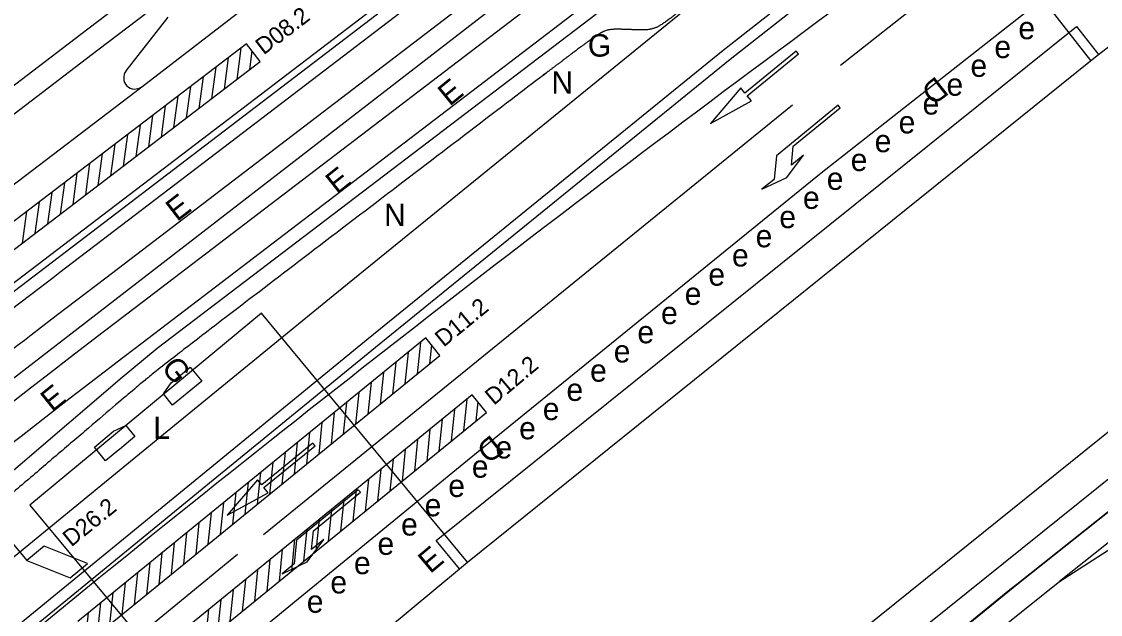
# Model space of a CAD drawing. Extents: x 81617 to 82144, y 454649 to 455150.
# Drawn here: x 81877.73 to 81925.8, y 454919.09 to 454945.52 of the extents above; entities that cross this region are included whole.
import ezdxf

# ---------------------------------------------------------------- set-up
doc = ezdxf.new("R2010")
doc.units = 0
for name, color, linetype in [('B-WE-OG-TOPOGRAFIE-G', 7, 'Continuous'), ('B-WE-VW-MARKERING-G', 7, 'Continuous'), ('N-OI-KL-VRI_KABEL_DETECTIE-G', 7, 'Continuous'), ('N-OI-KL-VRI_KABELGEUL-G', 7, 'Continuous'), ('N-OI-KL-VRI_LUS_DETECTIE-G', 7, 'Continuous'), ('N-OI-KL-VRI_LUS_DETECTIE-T18', 7, 'Continuous')]:
    doc.layers.add(name, color=color, linetype=linetype)

msp = doc.modelspace()

# ---------------------------------------------------------------- linework, layer by layer
at = {"layer": 'B-WE-OG-TOPOGRAFIE-G'}
for p, q in [((81900.482, 454960.292), (81880.371, 454944.941)), ((81923.402, 454955.563), (81908.992, 454944.223)), ((81923.712, 454955.17), (81909.304, 454943.832)), ((81925.37, 454943.778), (81916.494, 454955.166)), ((81925.72, 454944.049), (81935.606, 454951.727)), ((81927.735, 454950.065), (81913.364, 454938.756)), ((81881.134, 454944.252), (81888.032, 454949.528)), ((81883.083, 454942.614), (81889.238, 454947.349)), ((81907.441, 454946.156), (81891.612, 454933.292)), ((81882.384, 454943.318), (81884.261, 454945.72)), ((81880.371, 454944.941), (81861.954, 454930.868)), ((81908.992, 454944.223), (81893.179, 454931.372)), ((81909.304, 454943.832), (81893.495, 454930.984)), ((81864.605, 454928.508), (81883.083, 454942.614)), ((81913.364, 454938.756), (81897.603, 454925.947)), ((81891.612, 454933.292), (81884.055, 454927.107)), ((81888.418, 454932.525), (81878.092, 454923.965)), ((81897.597, 454921.411), (81888.418, 454932.525)), ((81893.179, 454931.372), (81885.624, 454925.189)), ((81893.495, 454930.984), (81885.941, 454924.802)), ((81884.055, 454927.107), (81874.789, 454919.522)), ((81897.603, 454925.947), (81890.058, 454919.772)), ((81885.941, 454924.802), (81876.995, 454917.479)), ((81878.092, 454923.965), (81887.313, 454912.861)), ((81890.058, 454919.772), (81881.911, 454913.103))]:
    msp.add_line(p, q, dxfattribs=at)
for points in [[(81873.49, 454927.861), (81874.235, 454928.464), (81874.684, 454928.824), (81874.834, 454928.943), (81875.133, 454929.183), (81876.035, 454929.897), (81876.336, 454930.134), (81876.944, 454930.61), (81877.553, 454931.084), (81877.859, 454931.32), (81878.164, 454931.557), (81879.083, 454932.264), (81879.697, 454932.734), (81880.618, 454933.44), (81881.483, 454934.1), (82053.484, 455065.539)], [(82052.863, 455062.717), (81907.219, 454951.42), (81881.918, 454932.086), (81881.368, 454931.665), (81879.897, 454930.54), (81879.014, 454929.861), (81878.133, 454929.178), (81876.818, 454928.147), (81876.529, 454927.916), (81876.383, 454927.802), (81875.945, 454927.452), (81875.222, 454926.872), (81874.931, 454926.636), (81874.646, 454926.404), (81874.501, 454926.287), (81873.923, 454925.815), (81873.138, 454925.168), (81872.64, 454924.754), (81871.896, 454924.132), (81871.4, 454923.716), (81870.675, 454923.104)], [(82053.734, 455061.577), (81908.09, 454950.28), (81882.79, 454930.946), (81882.24, 454930.525), (81880.77, 454929.401), (81879.891, 454928.725), (81879.015, 454928.046), (81877.708, 454927.021), (81877.419, 454926.791), (81877.274, 454926.677), (81876.842, 454926.332), (81876.122, 454925.754), (81875.835, 454925.522), (81875.549, 454925.289), (81875.405, 454925.173), (81874.834, 454924.706), (81874.053, 454924.062), (81873.558, 454923.651), (81872.817, 454923.032), (81872.324, 454922.618), (81871.758, 454922.14)], [(81908.893, 454909.665), (81922.078, 454920.426), (81934.059, 454929.942), (81952.813, 454944.436), (81970.927, 454957.964), (81989.889, 454971.628), (82009.083, 454984.966), (82010.714, 454986.077), (82028.879, 454998.275), (82047.264, 455010.138), (82051.217, 455012.627), (82070.774, 455024.747), (82077.174, 455028.646), (82100.034, 455042.055), (82099.927, 455042.255), (82105.495, 455045.472), (82101.819, 455050.382), (82106.416, 455053.06)], [(82110.864, 455047.248), (82106.595, 455044.529), (82093.157, 455036.793), (82086.193, 455032.73), (82077.781, 455027.741), (82071.319, 455023.811), (82051.792, 455011.702), (82032.005, 454998.954), (82011.355, 454985.186), (81991.431, 454971.342), (81971.574, 454957.059), (81953.642, 454943.677), (81934.749, 454929.095), (81934.668, 454929.059), (81923.982, 454920.562)], [(82110.864, 455047.248), (82106.595, 455044.529), (82093.157, 455036.793), (82086.193, 455032.73), (82077.781, 455027.741), (82071.319, 455023.811), (82051.792, 455011.702), (82032.005, 454998.954), (82011.355, 454985.186), (81991.431, 454971.342), (81971.574, 454957.059), (81953.642, 454943.677), (81934.749, 454929.095), (81934.668, 454929.059), (81923.982, 454920.562)], [(81877.287, 454932.693), (81878.516, 454933.638), (81879.132, 454934.109), (81879.439, 454934.345), (81887.3, 454940.351), (81901.614, 454951.29), (81901.778, 454951.416), (81947.621, 454986.447)], [(82009.226, 454984.737), (81990.032, 454971.399), (81971.07, 454957.735), (81952.956, 454944.207), (81934.202, 454929.713), (81934.033, 454929.927), (81922.078, 454920.426), (81921.763, 454920.179), (81908.891, 454909.667)], [(81978.164, 454966.737), (81944.138, 454941.42), (81944.109, 454941.37), (81943.803, 454941.123), (81933.963, 454933.496), (81933.581, 454933.203), (81906.906, 454911.73)], [(81873.083, 454921.869), (81875.385, 454923.83), (81882.216, 454929.671), (81883.773, 454930.953), (81919.061, 454957.857), (81919.157, 454957.774)], [(81901.315, 454952.138), (81867.262, 454926.143)], [(81901.497, 454951.9), (81867.49, 454925.94)], [(81897.244, 454921.116), (81896.206, 454922.384), (81924.728, 454945.293), (81925.72, 454944.049)], [(81862.719, 454930.188), (81881.134, 454944.252)], [(81897.244, 454921.116), (81897.603, 454921.415), (81925.363, 454943.772), (81925.72, 454944.049)], [(81908.032, 454910.56), (81934.945, 454932.197), (81933.963, 454933.496)], [(81884.39, 454929.406), (81885.248, 454930.11), (81885.755, 454929.491), (81884.451, 454928.421), (81884.047, 454928.92), (81884.39, 454929.406)], [(81882.369, 454927.516), (81882.782, 454927.014), (81882.086, 454926.441), (81882.069, 454926.423), (81881.474, 454925.937), (81880.973, 454926.548), (81881.831, 454927.252), (81882.369, 454927.516)], [(81885.624, 454925.189), (81876.617, 454917.816)], [(81888.57, 454911.351), (81887.313, 454912.861), (81897.244, 454921.116)], [(81909.649, 454908.88), (81921.982, 454918.972), (81923.977, 454920.559), (81923.982, 454920.562)]]:
    msp.add_lwpolyline(points, dxfattribs=at)
msp.add_arc((81882.778, 454943.01), 0.5, 142.0128, 307.5725, dxfattribs=at)
at = {"layer": 'B-WE-VW-MARKERING-G'}
for p, q in [((81911.696, 454956.155), (81875.824, 454928.411)), ((81924.585, 454951.725), (81914.212, 454943.562)), ((81912.086, 454941.793), (81888.51, 454922.632)), ((81914.108, 454941.789), (81911.363, 454939.538)), ((81912.115, 454939.961), (81914.203, 454941.673)), ((81914.203, 454941.673), (81914.108, 454941.789)), ((81912.032, 454939.116), (81912.115, 454939.961)), ((81911.363, 454939.538), (81911.258, 454938.482)), ((81911.835, 454938.567), (81912.573, 454939.56)), ((81912.573, 454939.56), (81912.032, 454939.116)), ((81910.717, 454938.039), (81911.835, 454938.567)), ((81911.258, 454938.482), (81910.717, 454938.039)), ((81892.729, 454924.649), (81889.984, 454922.399)), ((81890.736, 454922.821), (81892.824, 454924.533)), ((81892.824, 454924.533), (81892.729, 454924.649)), ((81890.653, 454921.977), (81890.736, 454922.821)), ((81889.984, 454922.399), (81889.879, 454921.343)), ((81890.456, 454921.428), (81891.194, 454922.421)), ((81891.194, 454922.421), (81890.653, 454921.977)), ((81887.349, 454921.754), (81876.908, 454913.208)), ((81889.338, 454920.899), (81890.456, 454921.428)), ((81889.879, 454921.343), (81889.338, 454920.899))]:
    msp.add_line(p, q, dxfattribs=at)
msp.add_lwpolyline([(81923.982, 454920.562), (81953.271, 454939.419), (81956.877, 454942.19), (81975.968, 454956.394), (81988.846, 454965.674), (81997.288, 454971.657), (81999.1, 454972.933), (82016.799, 454985.128), (82034.713, 454996.986), (82035.2, 454997.305), (82053.989, 455009.375), (82072.988, 455021.104), (82079.577, 455025.118), (82111.521, 455043.928), (82112.794, 455044.726)], dxfattribs=at)
for points in [[(81908.421, 454940.974), (81910.247, 454941.979), (81910.058, 454942.211), (81912.344, 454944.076), (81912.249, 454944.192), (81909.963, 454942.328), (81909.773, 454942.56)], [(81886.887, 454923.509), (81888.712, 454924.514), (81888.523, 454924.746), (81890.809, 454926.61), (81890.714, 454926.726), (81888.428, 454924.862), (81888.238, 454925.095)]]:
    msp.add_lwpolyline(points, close=True, dxfattribs=at)
msp.add_arc((82446.303, 454224.11), 897, 126.319161, 129.387113, dxfattribs=at)
at = {"layer": 'N-OI-KL-VRI_KABEL_DETECTIE-G'}
msp.add_line((81876.232, 454923.568), (81877.957, 454921.492), dxfattribs=at)
at = {"layer": 'N-OI-KL-VRI_KABELGEUL-G'}
msp.add_open_spline([(81966.954, 454994.044), (81954.516, 454984.42), (81942.079, 454974.796), (81941.008, 454974.125), (81939.937, 454973.455), (81933.631, 454968.575), (81927.325, 454963.696), (81926.798, 454963.288), (81926.621, 454962.646), (81926.355, 454961.682), (81926.09, 454960.718), (81925.901, 454960.035), (81925.325, 454959.623), (81922.434, 454957.557), (81919.543, 454955.49), (81917.87, 454954.23), (81916.197, 454952.97), (81913.406, 454950.849), (81910.615, 454948.728), (81908.564, 454947.145), (81906.513, 454945.562), (81905.944, 454945.123), (81905.225, 454945.147), (81904.815, 454945.16), (81904.405, 454945.174), (81903.693, 454945.197), (81903.126, 454944.765), (81893.683, 454937.565), (81884.239, 454930.365), (81883.469, 454929.731), (81882.698, 454929.096), (81879.285, 454926.178), (81875.872, 454923.259), (81872.421, 454920.321), (81868.97, 454917.382), (81867.082, 454915.724), (81865.195, 454914.067), (81863.45, 454912.271), (81861.704, 454910.475), (81860.838, 454909.482), (81859.972, 454908.49), (81859.86, 454908.361), (81859.97, 454908.23), (81860.094, 454908.077), (81860.218, 454907.925), (81863.368, 454903.762), (81866.518, 454899.599), (81866.598, 454899.497), (81866.679, 454899.395)], degree=4, dxfattribs=at)
at = {"layer": 'N-OI-KL-VRI_LUS_DETECTIE-G'}
for p, q in [((81887.752, 454944.526), (81871.852, 454932.389)), ((81888.357, 454943.73), (81887.752, 454944.526)), ((81887.505, 454944.337), (81887.316, 454942.935)), ((81887.992, 454944.21), (81887.878, 454943.364)), ((81872.461, 454931.594), (81888.357, 454943.73)), ((81886.38, 454943.479), (81886.192, 454942.077)), ((81886.942, 454943.908), (81886.754, 454942.506)), ((81885.818, 454943.05), (81885.63, 454941.648)), ((81885.256, 454942.621), (81885.068, 454941.219)), ((81884.694, 454942.192), (81884.506, 454940.79)), ((81884.132, 454941.763), (81883.944, 454940.361)), ((81883.57, 454941.334), (81883.382, 454939.932)), ((81883.008, 454940.905), (81882.82, 454939.503)), ((81882.446, 454940.476), (81882.258, 454939.074)), ((81881.322, 454939.618), (81881.134, 454938.216)), ((81881.884, 454940.047), (81881.696, 454938.645)), ((81880.76, 454939.189), (81880.572, 454937.786)), ((81880.198, 454938.76), (81880.01, 454937.357)), ((81879.636, 454938.331), (81879.448, 454936.928)), ((81879.074, 454937.902), (81878.886, 454936.499)), ((81878.512, 454937.473), (81878.324, 454936.07)), ((81877.95, 454937.044), (81877.762, 454935.641)), ((81895.74, 454931.411), (81880.232, 454918.778)), ((81895.499, 454931.214), (81895.355, 454929.807)), ((81896.37, 454930.634), (81895.74, 454931.411)), ((81895.99, 454931.103), (81895.903, 454930.254)), ((81880.865, 454918.002), (81896.37, 454930.634)), ((81894.95, 454930.768), (81894.807, 454929.361)), ((81894.402, 454930.321), (81894.258, 454928.914)), ((81893.854, 454929.875), (81893.71, 454928.467)), ((81893.306, 454929.428), (81893.162, 454928.021)), ((81897.81, 454928.87), (81882.302, 454916.237)), ((81892.757, 454928.981), (81892.614, 454927.574)), ((81897.569, 454928.673), (81897.425, 454927.266)), ((81898.44, 454928.093), (81897.81, 454928.87)), ((81898.06, 454928.561), (81897.973, 454927.713)), ((81882.935, 454915.461), (81898.44, 454928.093)), ((81891.661, 454928.088), (81891.517, 454926.681)), ((81892.209, 454928.535), (81892.066, 454927.128)), ((81897.021, 454928.226), (81896.877, 454926.82)), ((81891.113, 454927.642), (81890.969, 454926.234)), ((81896.472, 454927.78), (81896.329, 454926.373)), ((81890.565, 454927.195), (81890.421, 454925.788)), ((81895.924, 454927.333), (81895.78, 454925.926)), ((81890.016, 454926.749), (81889.873, 454925.341)), ((81895.376, 454926.887), (81895.232, 454925.48)), ((81889.468, 454926.302), (81889.325, 454924.894)), ((81894.828, 454926.44), (81894.684, 454925.033)), ((81888.92, 454925.855), (81888.776, 454924.448)), ((81894.28, 454925.994), (81894.136, 454924.586)), ((81888.372, 454925.409), (81888.228, 454924.001)), ((81893.731, 454925.547), (81893.588, 454924.14)), ((81887.824, 454924.962), (81887.68, 454923.555)), ((81893.183, 454925.1), (81893.039, 454923.693)), ((81887.275, 454924.516), (81887.132, 454923.108)), ((81892.635, 454924.654), (81892.491, 454923.247)), ((81886.727, 454924.069), (81886.584, 454922.661)), ((81891.539, 454923.761), (81891.395, 454922.353)), ((81892.087, 454924.207), (81891.943, 454922.8)), ((81886.179, 454923.623), (81886.035, 454922.215)), ((81890.99, 454923.314), (81890.847, 454921.907)), ((81885.631, 454923.176), (81885.487, 454921.768)), ((81890.442, 454922.868), (81890.298, 454921.46)), ((81885.083, 454922.729), (81884.939, 454921.322)), ((81889.894, 454922.421), (81889.75, 454921.013)), ((81878.729, 454922.127), (81877.957, 454921.492)), ((81880.663, 454921.356), (81878.729, 454922.127)), ((81883.986, 454921.836), (81883.842, 454920.428)), ((81884.534, 454922.283), (81884.391, 454920.875)), ((81889.346, 454921.975), (81889.202, 454920.567)), ((81877.957, 454921.492), (81879.89, 454920.72)), ((81879.89, 454920.72), (81880.663, 454921.356)), ((81883.438, 454921.39), (81883.294, 454919.982)), ((81888.798, 454921.528), (81888.654, 454920.12)), ((81882.89, 454920.943), (81882.746, 454919.535)), ((81888.249, 454921.081), (81888.106, 454919.674)), ((81882.342, 454920.497), (81882.198, 454919.088)), ((81887.701, 454920.635), (81887.557, 454919.227)), ((81881.793, 454920.05), (81881.65, 454918.642)), ((81887.153, 454920.188), (81887.009, 454918.78)), ((81881.245, 454919.603), (81881.101, 454918.195)), ((81886.605, 454919.742), (81886.461, 454918.334)), ((81880.697, 454919.157), (81880.611, 454918.314)), ((81886.057, 454919.295), (81885.913, 454917.887))]:
    msp.add_line(p, q, dxfattribs=at)

# ---------------------------------------------------------------- texts
at = {"layer": 'B-WE-OG-TOPOGRAFIE-G'}
for s, p in [('e', (81922.145, 454944.731)), ('G', (81902.961, 454943.955)), ('e', (81921.077, 454943.891)), ('e', (81920.01, 454943.052)), ('N', (81901.34, 454942.3)), ('e', (81918.943, 454942.212)), ('e', (81917.876, 454941.373)), ('e', (81916.809, 454940.533)), ('e', (81915.742, 454939.694)), ('e', (81914.674, 454938.855)), ('e', (81913.607, 454938.015)), ('e', (81912.547, 454937.167)), ('N', (81893.882, 454936.401)), ('e', (81911.493, 454936.311)), ('e', (81910.439, 454935.455)), ('e', (81909.385, 454934.599)), ('e', (81908.332, 454933.743)), ('e', (81907.278, 454932.887)), ('e', (81906.224, 454932.031)), ('e', (81905.17, 454931.175)), ('e', (81904.116, 454930.319)), ('e', (81903.062, 454929.463)), ('e', (81902.008, 454928.607)), ('e', (81900.954, 454927.751)), ('L', (81883.6, 454926.91)), ('e', (81899.9, 454926.895)), ('e', (81898.846, 454926.039)), ('e', (81897.792, 454925.183)), ('e', (81896.742, 454924.323)), ('e', (81895.691, 454923.463)), ('e', (81894.64, 454922.603)), ('e', (81893.589, 454921.743)), ('e', (81892.539, 454920.884)), ('e', (81891.488, 454920.024)), ('e', (81890.437, 454919.164))]:
    msp.add_text(s, height=1, dxfattribs=at).set_placement(p)
for s, rotation, p in [('E', 39.2391, (81896.801, 454941.713)), ('D', 218.2671, (81918.491, 454943.115)), ('E', 38.5717, (81891.789, 454937.78)), ('E', 37.6326, (81884.654, 454936.574)), ('G', 307.8617, (81883.918, 454930.085)), ('E', 38.6732, (81879.091, 454928.075)), ('D', 218.9989, (81898.666, 454927.138)), ('E', 40.0197, (81895.934, 454920.874))]:
    msp.add_text(s, height=1, rotation=rotation, dxfattribs=at).set_placement(p)
at = {"layer": 'N-OI-KL-VRI_LUS_DETECTIE-T18'}
for s, rotation, p in [('D08.2', 37.3715, (81888.515, 454944.006)), ('D11.2', 39.4343, (81896.536, 454930.977)), ('D12.2', 40.0605, (81898.773, 454928.385)), ('D26.2', 38.9894, (81879.945, 454922.073))]:
    msp.add_text(s, height=0.75, rotation=rotation, dxfattribs=at).set_placement(p)

doc.saveas('drawing.dxf')
